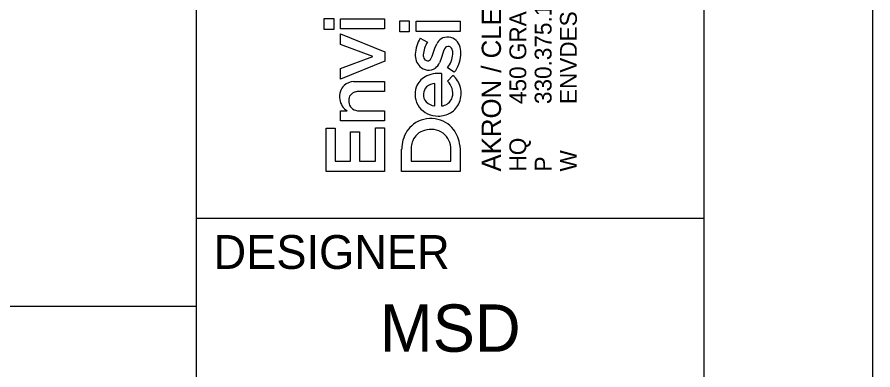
# Model space of a CAD drawing. Extents: x -17.1 to 34, y 0 to 22.
# Drawn here: x 31.469 to 34, y 2.552 to 3.594 of the extents above; entities that cross this region are included whole.
import ezdxf

# ---------------------------------------------------------------- set-up
doc = ezdxf.new("R2010")
doc.units = 0
for name, color, linetype in [('_CIVIL_CONSTRUCTION', 7, 'Continuous'), ('RW_X_CL', 7, 'Continuous'), ('RW_X_CL_100_Cardinal_Points', 7, 'Continuous'), ('RW_X_Esmt_SH', 7, 'Continuous')]:
    doc.layers.add(name, color=color, linetype=linetype)

msp = doc.modelspace()

# ---------------------------------------------------------------- linework, layer by layer
at = {"layer": '_CIVIL_CONSTRUCTION'}
msp.add_lwpolyline([(0, 0), (34, 0), (34, 22), (0, 22)], close=True, dxfattribs=at)
at = {"layer": 'RW_X_CL'}
for p, q in [((32, 0.5), (32, 21.5)), ((32, 3), (33.5, 3))]:
    msp.add_line(p, q, dxfattribs=at)
msp.add_lwpolyline([(1.5, 21.5), (33.5, 21.5), (33.5, 0.5), (1.5, 0.5)], close=True, dxfattribs=at)
at = {"layer": 'RW_X_CL_100_Cardinal_Points'}
msp.add_line((25.1966, 2.74), (32, 2.74), dxfattribs=at)
at = {"layer": 'RW_X_Esmt_SH'}
for p, q in [((32.3771, 3.5582), (32.3771, 3.5903)), ((32.3771, 3.5903), (32.4054, 3.5903)), ((32.4054, 3.5903), (32.4054, 3.5582)), ((32.4254, 3.5594), (32.4254, 3.5893)), ((32.4254, 3.5893), (32.5557, 3.5893)), ((32.5557, 3.5893), (32.5557, 3.5594)), ((32.6005, 3.5511), (32.6005, 3.5832)), ((32.6005, 3.5832), (32.6289, 3.5832)), ((32.6289, 3.5832), (32.6289, 3.5511)), ((32.6489, 3.5523), (32.6489, 3.5822)), ((32.6489, 3.5822), (32.7792, 3.5822)), ((32.7792, 3.5822), (32.7792, 3.5523)), ((32.4054, 3.5582), (32.3771, 3.5582)), ((32.5557, 3.5594), (32.4254, 3.5594)), ((32.4254, 3.5133), (32.4254, 3.5446)), ((32.4254, 3.5446), (32.5567, 3.4913)), ((32.6289, 3.5511), (32.6005, 3.5511)), ((32.7792, 3.5523), (32.6489, 3.5523)), ((32.6615, 3.5321), (32.6827, 3.5203)), ((32.5212, 3.478), (32.4254, 3.5133)), ((32.6967, 3.4787), (32.7048, 3.5026)), ((32.7048, 3.5026), (32.7104, 3.5153)), ((32.7298, 3.4933), (32.7221, 3.4688)), ((32.7334, 3.501), (32.7298, 3.4933)), ((32.4254, 3.4429), (32.5212, 3.478)), ((32.5567, 3.4913), (32.5567, 3.4644)), ((32.693, 3.4712), (32.6967, 3.4787)), ((32.7221, 3.4688), (32.7182, 3.4592)), ((32.5567, 3.4644), (32.4254, 3.4109)), ((32.4254, 3.4109), (32.4254, 3.4429)), ((32.7621, 3.4314), (32.742, 3.4447)), ((32.7245, 3.4275), (32.7246, 3.3319)), ((32.7423, 3.4046), (32.7577, 3.422)), ((32.4644, 3.404), (32.4729, 3.4044)), ((32.4729, 3.4044), (32.5557, 3.4044)), ((32.5557, 3.4044), (32.5557, 3.3746)), ((32.7049, 3.3318), (32.7049, 3.3983)), ((32.5557, 3.3746), (32.4814, 3.3746)), ((32.4254, 3.2875), (32.4254, 3.3173)), ((32.4254, 3.3173), (32.4455, 3.3173)), ((32.4822, 3.3173), (32.5557, 3.3173)), ((32.5557, 3.3173), (32.5557, 3.2876)), ((32.7036, 3.3317), (32.7049, 3.3318)), ((32.383, 3.1379), (32.383, 3.266)), ((32.383, 3.266), (32.4101, 3.266)), ((32.4101, 3.266), (32.4101, 3.1683)), ((32.5557, 3.2876), (32.4254, 3.2875)), ((32.5286, 3.1683), (32.5286, 3.2672)), ((32.5286, 3.2672), (32.5557, 3.2672)), ((32.5557, 3.2672), (32.5557, 3.1379)), ((32.455, 3.1683), (32.455, 3.2549)), ((32.455, 3.2549), (32.4822, 3.2549)), ((32.4822, 3.2549), (32.4822, 3.1683)), ((32.7785, 3.215), (32.7792, 3.2021)), ((32.6064, 3.138), (32.6064, 3.204)), ((32.6347, 3.2118), (32.6341, 3.2023)), ((32.6341, 3.2023), (32.6341, 3.1684)), ((32.7515, 3.1683), (32.7515, 3.2024)), ((32.7792, 3.2021), (32.7792, 3.138)), ((32.4101, 3.1683), (32.455, 3.1683)), ((32.4822, 3.1683), (32.5286, 3.1683)), ((32.6341, 3.1684), (32.7515, 3.1683)), ((32.5557, 3.1379), (32.383, 3.1379)), ((32.7792, 3.138), (32.6064, 3.138))]:
    msp.add_line(p, q, dxfattribs=at)
for points in [[(32.3771, 3.5582), (32.3771, 3.5903), (32.4054, 3.5903), (32.4054, 3.5582)], [(32.4254, 3.5594), (32.4254, 3.5893), (32.5557, 3.5893), (32.5557, 3.5594)], [(32.6005, 3.5511), (32.6005, 3.5832), (32.6289, 3.5832), (32.6289, 3.5511)], [(32.6489, 3.5523), (32.6489, 3.5822), (32.7792, 3.5822), (32.7792, 3.5523)], [(32.4254, 3.4109), (32.4254, 3.4429), (32.5212, 3.478), (32.4254, 3.5133), (32.4254, 3.5446), (32.5567, 3.4913), (32.5567, 3.4644)], [(32.383, 3.1379), (32.383, 3.266), (32.4101, 3.266), (32.4101, 3.1683), (32.455, 3.1683), (32.455, 3.2549), (32.4822, 3.2549), (32.4822, 3.1683), (32.5286, 3.1683), (32.5286, 3.2672), (32.5557, 3.2672), (32.5557, 3.1379)]]:
    msp.add_lwpolyline(points, close=True, dxfattribs=at)
for points in [[(32.6615, 3.5321), (32.6827, 3.5203)], [(32.693, 3.4712), (32.6967, 3.4787), (32.7048, 3.5026), (32.7104, 3.5153)], [(32.7334, 3.501), (32.7298, 3.4933), (32.7221, 3.4688), (32.7182, 3.4592)], [(32.7621, 3.4314), (32.742, 3.4447)], [(32.7245, 3.4275), (32.7246, 3.3319)], [(32.7423, 3.4046), (32.7577, 3.422)], [(32.4644, 3.404), (32.4729, 3.4044), (32.5557, 3.4044), (32.5557, 3.3746), (32.4814, 3.3746)], [(32.7036, 3.3317), (32.7049, 3.3318), (32.7049, 3.3983)], [(32.4254, 3.2875), (32.4254, 3.3173), (32.4455, 3.3173)], [(32.4822, 3.3173), (32.5557, 3.3173), (32.5557, 3.2876), (32.4254, 3.2875)], [(32.7785, 3.215), (32.7792, 3.2021), (32.7792, 3.138), (32.6064, 3.138)], [(32.6064, 3.138), (32.6064, 3.204)], [(32.6347, 3.2118), (32.6341, 3.2023), (32.6341, 3.1684), (32.7515, 3.1683), (32.7515, 3.2024)]]:
    msp.add_lwpolyline(points, dxfattribs=at)
for centre, radius, start, end in [((32.7364, 3.4826), 0.0897, 146.531, 178.7571), ((32.7364, 3.4826), 0.0897, 146.531, 178.7571), ((32.7452, 3.4789), 0.0749, 146.5112, 176.9101), ((32.7452, 3.4789), 0.0749, 146.5112, 176.9101), ((32.7466, 3.4971), 0.0405, 125.5118, 153.4159), ((32.7466, 3.4971), 0.0405, 125.5118, 153.4159), ((32.7406, 3.5026), 0.0326, 80.1719, 122.5197), ((32.7406, 3.5026), 0.0326, 80.1719, 122.5197), ((32.7428, 3.4982), 0.0367, 47.7934, 84.6892), ((32.7428, 3.4982), 0.0367, 47.7934, 84.6892), ((32.7379, 3.4946), 0.0427, 14.9966, 46.2063), ((32.7379, 3.4946), 0.0427, 14.9966, 46.2063), ((32.7438, 3.4963), 0.0114, 76.6609, 155.7053), ((32.7438, 3.4963), 0.0114, 76.6609, 155.7053), ((32.744, 3.4951), 0.0126, 21.5098, 78.5262), ((32.744, 3.4951), 0.0126, 21.5098, 78.5262), ((32.7259, 3.4877), 0.0321, 354.5726, 22.068), ((32.7259, 3.4877), 0.0321, 354.5726, 22.068), ((32.7104, 3.4867), 0.0712, 355.8306, 15.3914), ((32.7104, 3.4867), 0.0712, 355.8306, 15.3914), ((32.6967, 3.4824), 0.0501, 177.5366, 222.7932), ((32.6967, 3.4824), 0.0501, 177.5366, 222.7932), ((32.6931, 3.4823), 0.0228, 178.4747, 211.0868), ((32.6931, 3.4823), 0.0228, 178.4747, 211.0868), ((32.6833, 3.4767), 0.0115, 212.2368, 268.3777), ((32.6833, 3.4767), 0.0115, 212.2368, 268.3777), ((32.6834, 3.4759), 0.0107, 267.716, 333.7337), ((32.6834, 3.4759), 0.0107, 267.716, 333.7337), ((32.6825, 3.4915), 0.0757, 321.811, 354.7969), ((32.6825, 3.4915), 0.0757, 321.811, 354.7969), ((32.6895, 3.4882), 0.0922, 321.9777, 355.8738), ((32.6895, 3.4882), 0.0922, 321.9777, 355.8738), ((32.686, 3.4753), 0.0375, 225.9854, 302.4797), ((32.686, 3.4753), 0.0375, 225.9854, 302.4797), ((32.681, 3.4758), 0.0408, 308.0877, 335.9874), ((32.681, 3.4758), 0.0408, 308.0877, 335.9874), ((32.7024, 3.3691), 0.0558, 118.8308, 160.6244), ((32.7024, 3.3691), 0.0558, 118.8308, 160.6244), ((32.7152, 3.3441), 0.0838, 83.615, 118.2876), ((32.7152, 3.3441), 0.0838, 83.615, 118.2876), ((32.7174, 3.3717), 0.0644, 13.5336, 51.3615), ((32.7174, 3.3717), 0.0644, 13.5336, 51.3615), ((32.4635, 3.3626), 0.0402, 132.2219, 161.6818), ((32.4635, 3.3626), 0.0402, 132.2219, 161.6818), ((32.4687, 3.3543), 0.0499, 94.9696, 130.2225), ((32.4687, 3.3543), 0.0499, 94.9696, 130.2225), ((32.7079, 3.3561), 0.0424, 94.008, 130.8817), ((32.7079, 3.3561), 0.0424, 94.008, 130.8817), ((32.7038, 3.3656), 0.0549, 19.0357, 45.4406), ((32.7038, 3.3656), 0.0549, 19.0357, 45.4406), ((32.4787, 3.3582), 0.056, 162.2736, 187.7919), ((32.4787, 3.3582), 0.056, 162.2736, 187.7919), ((32.4748, 3.3487), 0.025, 103.6865, 182.2187), ((32.4748, 3.3487), 0.025, 103.6865, 182.2187), ((32.4811, 3.3286), 0.046, 89.6049, 105.3284), ((32.4811, 3.3286), 0.046, 89.6049, 105.3284), ((32.7104, 3.3661), 0.0644, 160.5201, 215.7831), ((32.7104, 3.3661), 0.0644, 160.5201, 215.7831), ((32.7017, 3.365), 0.0311, 175.0013, 223.283), ((32.7017, 3.365), 0.0311, 175.0013, 223.283), ((32.7005, 3.3663), 0.0298, 132.9851, 177.179), ((32.7005, 3.3663), 0.0298, 132.9851, 177.179), ((32.7107, 3.3697), 0.047, 344.6059, 17.007), ((32.7107, 3.3697), 0.047, 344.6059, 17.007), ((32.7064, 3.3692), 0.0758, 339.3542, 13.3785), ((32.7064, 3.3692), 0.0758, 339.3542, 13.3785), ((32.4703, 3.358), 0.0476, 188.962, 238.7037), ((32.4703, 3.358), 0.0476, 188.962, 238.7037), ((32.4773, 3.3456), 0.0276, 175.5854, 255.1439), ((32.4773, 3.3456), 0.0276, 175.5854, 255.1439), ((32.7089, 3.3736), 0.0423, 225.0619, 262.7974), ((32.7089, 3.3736), 0.0423, 225.0619, 262.7974), ((32.7224, 3.3671), 0.035, 288.0077, 343.5508), ((32.7224, 3.3671), 0.035, 288.0077, 343.5508), ((32.7189, 3.3652), 0.0626, 300.9427, 338.7323), ((32.7189, 3.3652), 0.0626, 300.9427, 338.7323), ((32.4818, 3.3595), 0.0422, 254.0916, 270.5284), ((32.4818, 3.3595), 0.0422, 254.0916, 270.5284), ((32.7125, 3.3705), 0.0687, 217.7452, 271.6543), ((32.7125, 3.3705), 0.0687, 217.7452, 271.6543), ((32.7247, 3.3522), 0.0202, 269.7003, 294.8711), ((32.7247, 3.3522), 0.0202, 269.7003, 294.8711), ((32.6923, 3.2079), 0.0864, 81.194, 125.9984), ((32.6923, 3.2079), 0.0864, 81.194, 125.9984), ((32.6946, 3.2113), 0.0827, 37.8521, 82.402), ((32.6946, 3.2113), 0.0827, 37.8521, 82.402), ((32.7155, 3.3724), 0.0706, 269.2048, 300.3341), ((32.7155, 3.3724), 0.0706, 269.2048, 300.3341), ((32.6939, 3.2089), 0.0865, 127.2362, 165.148), ((32.6939, 3.2089), 0.0865, 127.2362, 165.148), ((32.6889, 3.2078), 0.054, 106.1881, 157.3861), ((32.6889, 3.2078), 0.054, 106.1881, 157.3861), ((32.6928, 3.1986), 0.0639, 55.6727, 107.2093), ((32.6928, 3.1986), 0.0639, 55.6727, 107.2093), ((32.6929, 3.205), 0.0587, 357.4662, 52.2665), ((32.6929, 3.205), 0.0587, 357.4662, 52.2665), ((32.6859, 3.2057), 0.0931, 5.7333, 37.304), ((32.6859, 3.2057), 0.0931, 5.7333, 37.304), ((32.7143, 3.2028), 0.1078, 164.7861, 179.3704), ((32.7143, 3.2028), 0.1078, 164.7861, 179.3704), ((32.6983, 3.2039), 0.0641, 157.3571, 172.9275), ((32.6983, 3.2039), 0.0641, 157.3571, 172.9275)]:
    msp.add_arc(centre, radius, start, end, dxfattribs=at)

# ---------------------------------------------------------------- texts
for s, height, p in [('450 GRANT ST., AKRON, OH  44311', 0.049846, (32.9749, 3.3374)), ('AKRON / CLEVELAND / COLUMBUS', 0.056969, (32.9001, 3.138)), ('ENVDESIGNGROUP.COM', 0.049846, (33.1244, 3.3374)), ('330.375.1390', 0.049846, (33.0497, 3.3374)), ('HQ ', 0.04985, (32.9749, 3.138)), ('W', 0.0498, (33.1244, 3.138)), ('P', 0.0498, (33.0497, 3.138))]:
    msp.add_text(s, height=height, rotation=90, dxfattribs=at).set_placement(p)
for s, height, p in [('DESIGNER', 0.1, (32.05, 2.85)), ('MSD', 0.14, (32.5422, 2.605))]:
    msp.add_text(s, height=height, dxfattribs=at).set_placement(p)

doc.saveas('drawing.dxf')
